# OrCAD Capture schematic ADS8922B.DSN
size A
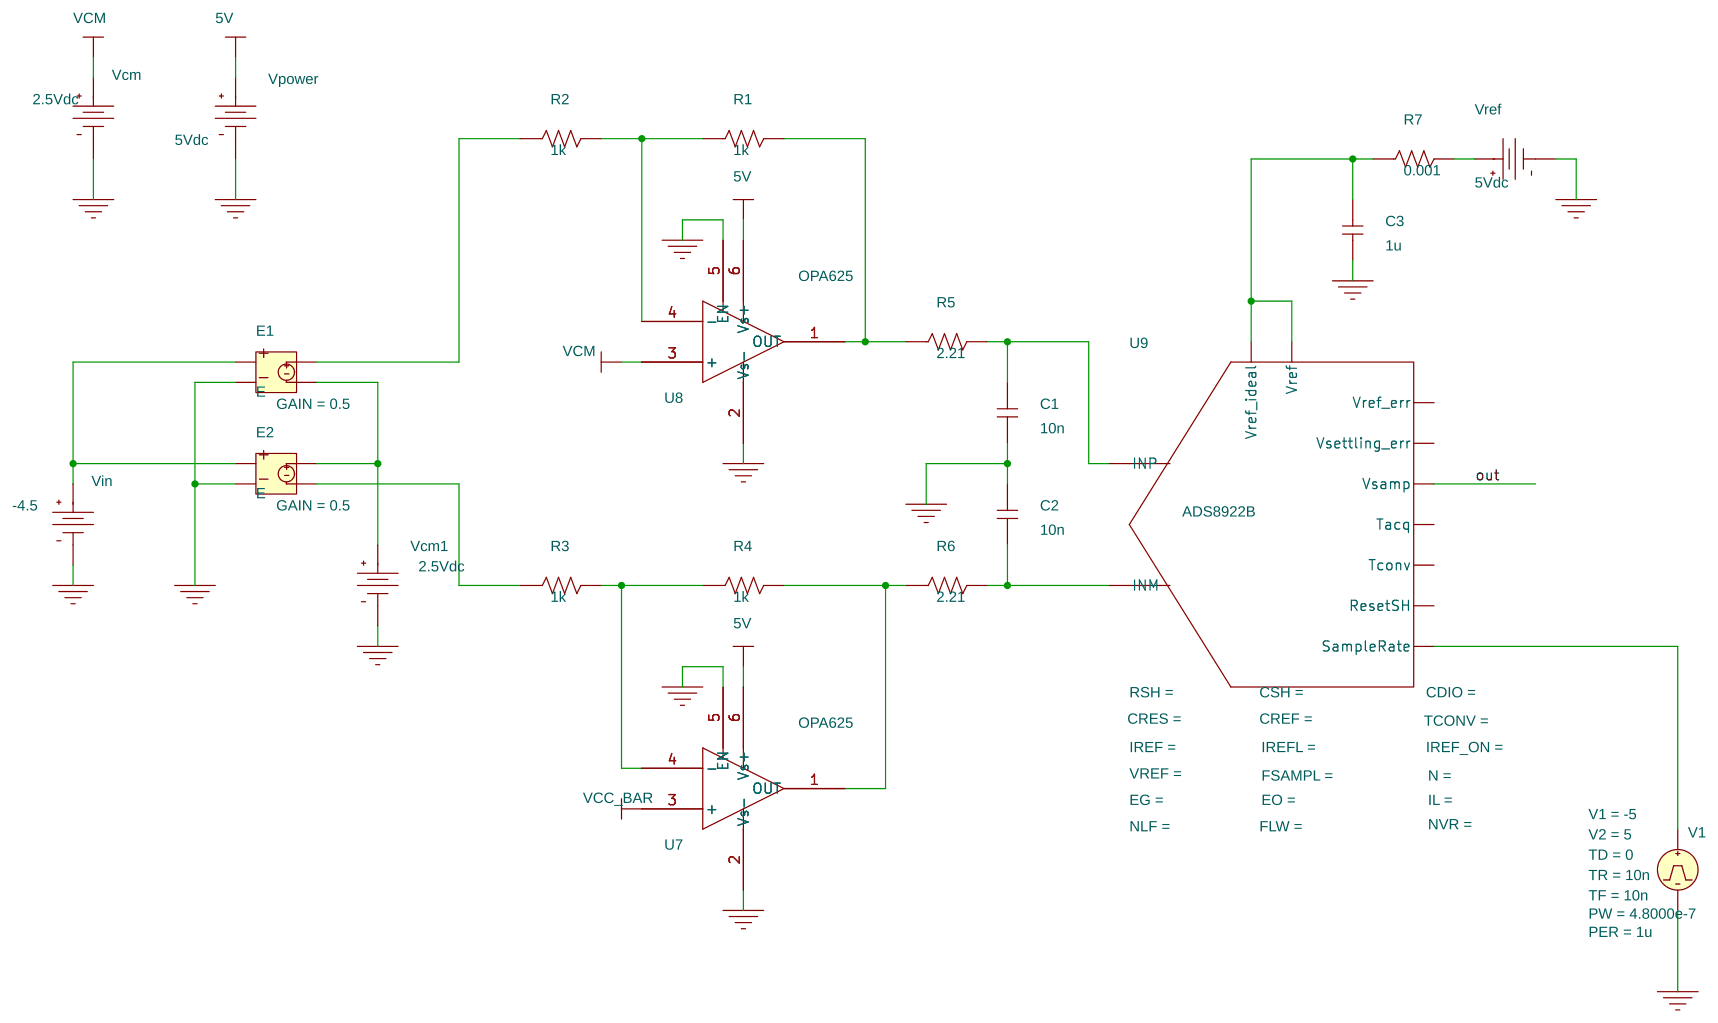
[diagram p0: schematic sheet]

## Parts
C1  10n  [cap196]
C2  10n  [cap196]
C3  1u  [cap196]
E1  E
E2  E
R1  1k  [AXRC05]
R2  1k  [AXRC05]
R3  1k  [AXRC05]
R4  1k  [AXRC05]
R5  2.21  [AXRC05]
R6  2.21  [AXRC05]
R7  0.001  [AXRC05]
U7  OPA625
U8  OPA625
U9  ADS8922B
V1  VPULSE
Vcm  VDC
Vcm1  VDC
Vin  VDC
Vpower  VDC
Vref  VDC

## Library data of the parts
C1-C3 = C
E1 E2 = E: GAIN: 0.5
R1-R7 = R
U7 U8 = OPA625: Testbenches: [{"testbenchurl":"https://software-dl.ti.com/pspice/esd/models/OPA625_V5.0.zip","testbenchopj":"OPA625/opa625.opj","testbenchdisplayname":"OPA625 PSPICE Model"}]; productURL: http://www.ti.com/document-viewer/OPA625/datasheet/
U9 = ADS8922B
V1 = VPULSE: AC: 0; AppProp: Pulse$Voltage$2$-1; DC: 0; PER: 1u; PW: 4.8000e-7; TD: 0; TF: 10n; TR: 10n; V1: -5; V2: 5
Vcm Vcm1 = VDC: DC: 2.5Vdc
Vin = VDC: DC: -4.5
Vpower Vref = VDC: DC: 5Vdc

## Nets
5V: U7.6(Vs+) U8.6(Vs+) Vpower.0(+)
0: C1.1 C2.2 C3.1 E1.2 E2.2 U7.2(Vs-) U7.5(EN) U8.2(Vs-) U8.5(EN) V1.2(-) Vcm.1(-) Vcm1.1(-) Vin.1(-) Vpower.1(-) Vref.1(-)
out: U9.Vsamp
Vcm: U7.3(+) U8.3(+) Vcm.0(+)
N21235: E1.3 R2.1
N21245: R1.1 R2.2 U8.4(-)
N21259: R1.2 R5.1 U8.1(OUT)
N21321: C3.2 R7.1 U9.Vref U9.Vref_ideal
N21339: R7.2 Vref.0(+)
N21559: C1.2 R5.2 U9.INP
N21577: E1.1 E2.1 Vin.0(+)
N21743: E1.4 E2.3 Vcm1.0(+)
N21879: E2.4 R3.1
N21943: C2.1 R6.2 U9.INM
N22033: R3.2 R4.1 U7.4(-)
N22047: R4.2 R6.1 U7.1(OUT)
N22093: U9.SampleRate V1.1(+)

Not connected (* = marked no-connect by the designer): U9 ResetSH Tacq Tconv Vref_err Vsettling_err
